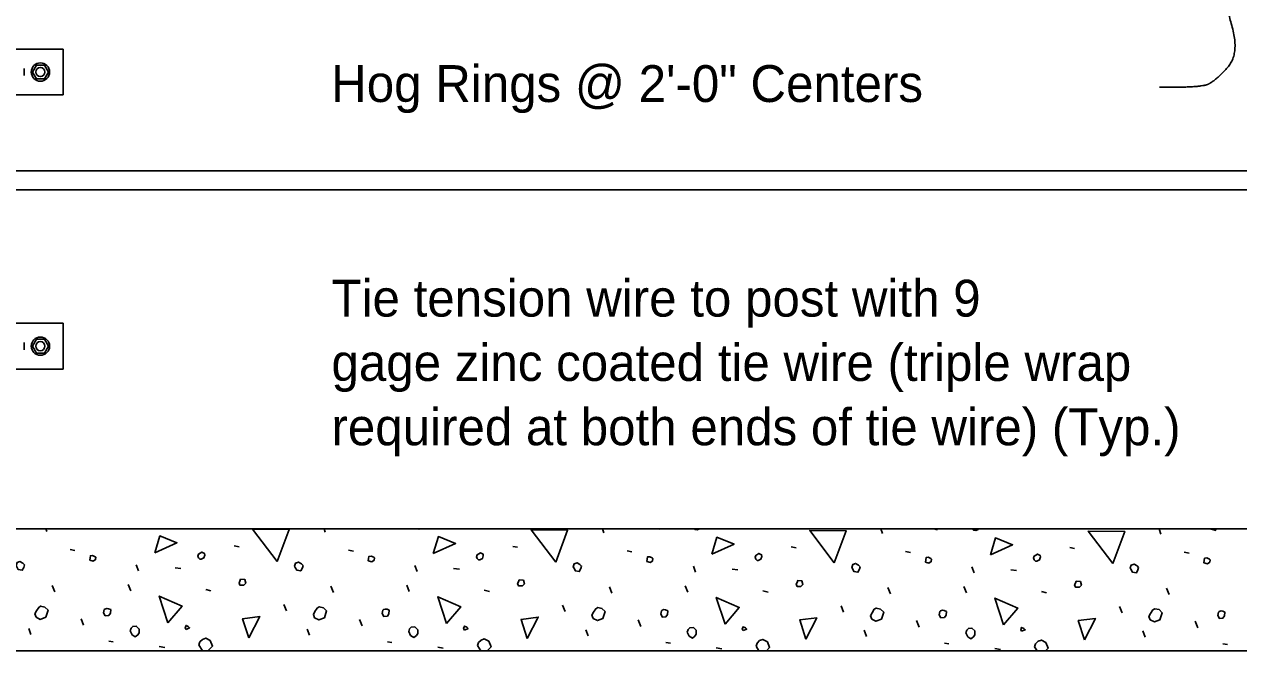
# Model space of a CAD drawing. Extents: x 0 to 41.2, y 0 to 26.
# Drawn here: x 12.4 to 19.04, y 13.8 to 17.23 of the extents above; entities that cross this region are included whole.
import ezdxf

# ---------------------------------------------------------------- set-up
doc = ezdxf.new("R2010")
doc.units = 0
for name, color, linetype in [('Dimension', 7, 'Continuous'), ('Miscellaneous', 7, 'Continuous'), ('SteelMisc', 7, 'Continuous'), ('SupstrConc', 7, 'Continuous'), ('TextStructures', 7, 'Continuous')]:
    doc.layers.add(name, color=color, linetype=linetype)

msp = doc.modelspace()

# ---------------------------------------------------------------- linework, layer by layer
at = {"layer": 'Dimension'}
msp.add_open_spline([(18.6095, 16.8868), (18.8324, 16.8833), (18.9173, 16.9222), (19.0482, 17.0709), (18.9633, 17.3684), (18.9208, 17.6337)], degree=2, dxfattribs=at)
at = {"layer": 'Miscellaneous'}
for p, q in [((12.5219, 14.4553), (12.5167, 14.4695)), ((14.0457, 14.4518), (14.0392, 14.4695)), ((15.5695, 14.4482), (15.5617, 14.4695)), ((15.8647, 14.4695), (15.8718, 14.4677)), ((17.0933, 14.4447), (17.0842, 14.4695)), ((17.3744, 14.4695), (17.3956, 14.4641)), ((18.6171, 14.4412), (18.6067, 14.4695)), ((18.8911, 14.4677), (18.9194, 14.4606)), ((12.6492, 14.3563), (12.6757, 14.351)), ((13.5472, 14.3775), (13.5737, 14.3722)), ((14.173, 14.3528), (14.1995, 14.3475)), ((15.071, 14.374), (15.0975, 14.3687)), ((16.5948, 14.3705), (16.6213, 14.3652)), ((18.1186, 14.3669), (18.1451, 14.3616)), ((15.6968, 14.3492), (15.7233, 14.3439)), ((17.2206, 14.3457), (17.2471, 14.3404)), ((18.7444, 14.3422), (18.7709, 14.3369)), ((13.0239, 14.2396), (13.0115, 14.2732)), ((13.2237, 14.2556), (13.2555, 14.252)), ((14.5477, 14.2361), (14.5354, 14.2697)), ((14.7475, 14.252), (14.7793, 14.2485)), ((16.0716, 14.2326), (16.0592, 14.2662)), ((16.2713, 14.2485), (16.3031, 14.2449)), ((17.5954, 14.229), (17.583, 14.2626)), ((17.7951, 14.2449), (17.8269, 14.2414)), ((12.5661, 14.1247), (12.5519, 14.1601)), ((12.9815, 14.13), (12.9674, 14.1654)), ((14.0899, 14.1212), (14.0757, 14.1566)), ((14.5053, 14.1265), (14.4912, 14.1619)), ((15.6137, 14.1177), (15.5996, 14.153)), ((16.0291, 14.123), (16.015, 14.1583)), ((17.5529, 14.1194), (17.5388, 14.1548)), ((13.3916, 14.1371), (13.4199, 14.13)), ((14.9154, 14.1336), (14.9437, 14.1265)), ((16.4392, 14.13), (16.4675, 14.123)), ((17.1375, 14.1141), (17.1234, 14.1495)), ((17.9631, 14.1265), (17.9913, 14.1194)), ((18.6613, 14.1106), (18.6472, 14.146)), ((13.8336, 14.0204), (13.8194, 14.0558)), ((15.3574, 14.0169), (15.3432, 14.0523)), ((16.8812, 14.0134), (16.867, 14.0487)), ((18.405, 14.0098), (18.3909, 14.0452)), ((12.7234, 13.9427), (12.7093, 13.978)), ((14.2472, 13.9391), (14.2331, 13.9745)), ((15.771, 13.9356), (15.7569, 13.9709)), ((17.2948, 13.9321), (17.2807, 13.9674)), ((18.8187, 13.9285), (18.8045, 13.9639)), ((12.4353, 13.8914), (12.4229, 13.925)), ((13.9591, 13.8879), (13.9467, 13.9214)), ((15.4829, 13.8843), (15.4705, 13.9179)), ((17.0067, 13.8808), (16.9943, 13.9144)), ((18.5305, 13.8772), (18.5181, 13.9108)), ((12.8613, 13.8543), (12.886, 13.8507)), ((13.1371, 13.826), (13.1671, 13.8207)), ((14.3851, 13.8507), (14.4099, 13.8472)), ((14.6609, 13.8224), (14.6909, 13.8171)), ((15.9089, 13.8472), (15.9337, 13.8437)), ((16.1847, 13.8189), (16.2147, 13.8136)), ((17.4327, 13.8437), (17.4575, 13.8401)), ((18.9565, 13.8401), (18.9813, 13.8366)), ((17.7085, 13.8154), (17.7386, 13.8101))]:
    msp.add_line(p, q, dxfattribs=at)
for points in [[(13.1123, 14.3386), (13.1406, 14.4306), (13.2343, 14.3934), (13.1123, 14.3386)], [(13.7823, 14.2909), (13.6479, 14.4677), (13.8477, 14.4659), (13.7823, 14.2909)], [(14.5442, 14.4695), (14.5566, 14.4677), (14.5607, 14.4695)], [(14.6361, 14.3351), (14.6644, 14.427), (14.7581, 14.3899), (14.6361, 14.3351)], [(15.3061, 14.2874), (15.1718, 14.4641), (15.3715, 14.4624), (15.3061, 14.2874)], [(16.0645, 14.4695), (16.068, 14.4659)], [(16.068, 14.4659), (16.0804, 14.4641), (16.0928, 14.4695)], [(16.1599, 14.3316), (16.1882, 14.4235), (16.2819, 14.3864), (16.1599, 14.3316)], [(16.8299, 14.2838), (16.6956, 14.4606), (16.8953, 14.4588), (16.8299, 14.2838)], [(17.5848, 14.4695), (17.5918, 14.4624)], [(17.5918, 14.4624), (17.6042, 14.4606), (17.6166, 14.4659), (17.6178, 14.4695)], [(17.6838, 14.328), (17.712, 14.42), (17.8057, 14.3828), (17.6838, 14.328)], [(18.3537, 14.2803), (18.2194, 14.4571), (18.4191, 14.4553), (18.3537, 14.2803)], [(12.3575, 14.2626), (12.3663, 14.2467), (12.3875, 14.2432), (12.3964, 14.2591), (12.3999, 14.2732), (12.3911, 14.2821), (12.3752, 14.2909), (12.3592, 14.2856), (12.3539, 14.2697), (12.3575, 14.2626)], [(12.757, 14.298), (12.7764, 14.2927), (12.7888, 14.3015), (12.7906, 14.3139), (12.787, 14.3174), (12.7729, 14.3245), (12.7605, 14.3227), (12.7588, 14.3104), (12.757, 14.298)], [(13.3598, 14.3033), (13.3669, 14.3033), (13.381, 14.3104), (13.3863, 14.3263), (13.3845, 14.3351), (13.3704, 14.3422), (13.3527, 14.3316), (13.3492, 14.321), (13.3527, 14.3104), (13.3598, 14.3033)], [(13.8813, 14.2591), (13.8901, 14.2432), (13.9113, 14.2396), (13.9202, 14.2556), (13.9237, 14.2697), (13.9149, 14.2785), (13.899, 14.2874), (13.8831, 14.2821), (13.8778, 14.2662), (13.8813, 14.2591)], [(14.2808, 14.2944), (14.3003, 14.2891), (14.3126, 14.298), (14.3144, 14.3104), (14.3109, 14.3139), (14.2967, 14.321), (14.2843, 14.3192), (14.2826, 14.3068), (14.2808, 14.2944)], [(14.8836, 14.2997), (14.8907, 14.2997), (14.9048, 14.3068), (14.9101, 14.3227), (14.9084, 14.3316), (14.8942, 14.3386), (14.8765, 14.328), (14.873, 14.3174), (14.8765, 14.3068), (14.8836, 14.2997)], [(15.4051, 14.2556), (15.4139, 14.2396), (15.4352, 14.2361), (15.444, 14.252), (15.4475, 14.2662), (15.4387, 14.275), (15.4228, 14.2838), (15.4069, 14.2785), (15.4016, 14.2626), (15.4051, 14.2556)], [(15.8046, 14.2909), (15.8241, 14.2856), (15.8364, 14.2944), (15.8382, 14.3068), (15.8347, 14.3104), (15.8205, 14.3174), (15.8082, 14.3157), (15.8064, 14.3033), (15.8046, 14.2909)], [(16.4074, 14.2962), (16.4145, 14.2962), (16.4286, 14.3033), (16.4339, 14.3192), (16.4322, 14.328), (16.418, 14.3351), (16.4004, 14.3245), (16.3968, 14.3139), (16.4004, 14.3033), (16.4074, 14.2962)], [(17.3284, 14.2874), (17.3479, 14.2821), (17.3603, 14.2909), (17.362, 14.3033), (17.3585, 14.3068), (17.3443, 14.3139), (17.332, 14.3121), (17.3302, 14.2997), (17.3284, 14.2874)], [(17.9312, 14.2927), (17.9383, 14.2927), (17.9525, 14.2997), (17.9578, 14.3157), (17.956, 14.3245), (17.9419, 14.3316), (17.9242, 14.321), (17.9206, 14.3104), (17.9242, 14.2997), (17.9312, 14.2927)], [(18.8523, 14.2838), (18.8717, 14.2785), (18.8841, 14.2874), (18.8858, 14.2997), (18.8823, 14.3033), (18.8682, 14.3104), (18.8558, 14.3086), (18.854, 14.2962), (18.8523, 14.2838)], [(16.9289, 14.252), (16.9378, 14.2361), (16.959, 14.2326), (16.9678, 14.2485), (16.9713, 14.2626), (16.9625, 14.2715), (16.9466, 14.2803), (16.9307, 14.275), (16.9254, 14.2591), (16.9289, 14.252)], [(18.4527, 14.2485), (18.4616, 14.2326), (18.4828, 14.229), (18.4916, 14.2449), (18.4952, 14.2591), (18.4863, 14.2679), (18.4704, 14.2768), (18.4545, 14.2715), (18.4492, 14.2556), (18.4527, 14.2485)], [(13.579, 14.1619), (13.6002, 14.1619), (13.6108, 14.1725), (13.6055, 14.1919), (13.5825, 14.1937), (13.579, 14.1831), (13.5737, 14.1742), (13.579, 14.1619), (13.5755, 14.1654)], [(15.1028, 14.1583), (15.124, 14.1583), (15.1346, 14.1689), (15.1293, 14.1884), (15.1064, 14.1901), (15.1028, 14.1795), (15.0975, 14.1707), (15.1028, 14.1583), (15.0993, 14.1619)], [(16.6266, 14.1548), (16.6478, 14.1548), (16.6585, 14.1654), (16.6531, 14.1848), (16.6302, 14.1866), (16.6266, 14.176), (16.6213, 14.1672), (16.6266, 14.1548), (16.6231, 14.1583)], [(18.1504, 14.1513), (18.1717, 14.1513), (18.1823, 14.1619), (18.177, 14.1813), (18.154, 14.1831), (18.1504, 14.1725), (18.1451, 14.1636), (18.1504, 14.1513), (18.1469, 14.1548)], [(13.1848, 13.955), (13.1371, 14.1018), (13.2626, 14.047), (13.1848, 13.955)], [(14.7086, 13.9515), (14.6609, 14.0982), (14.7864, 14.0434), (14.7086, 13.9515)], [(16.2324, 13.948), (16.1847, 14.0947), (16.3102, 14.0399), (16.2324, 13.948)], [(17.7562, 13.9444), (17.7085, 14.0911), (17.834, 14.0363), (17.7562, 13.9444)], [(12.4635, 13.9869), (12.4865, 13.9745), (12.5166, 13.9869), (12.5289, 14.024), (12.5113, 14.0417), (12.4883, 14.047), (12.4777, 14.0399), (12.4653, 14.0204), (12.4565, 14.0045), (12.4635, 13.9869)], [(12.833, 14.0098), (12.8418, 13.9939), (12.8613, 13.9957), (12.8701, 14.0081), (12.8719, 14.0275), (12.8595, 14.0328), (12.8507, 14.0346), (12.8401, 14.031), (12.8365, 14.0275), (12.833, 14.0098)], [(13.9874, 13.9833), (14.0103, 13.9709), (14.0404, 13.9833), (14.0528, 14.0204), (14.0351, 14.0381), (14.0121, 14.0434), (14.0015, 14.0363), (13.9891, 14.0169), (13.9803, 14.001), (13.9874, 13.9833)], [(14.3568, 14.0063), (14.3657, 13.9904), (14.3851, 13.9922), (14.3939, 14.0045), (14.3957, 14.024), (14.3833, 14.0293), (14.3745, 14.031), (14.3639, 14.0275), (14.3604, 14.024), (14.3568, 14.0063)], [(15.5112, 13.9798), (15.5342, 13.9674), (15.5642, 13.9798), (15.5766, 14.0169), (15.5589, 14.0346), (15.5359, 14.0399), (15.5253, 14.0328), (15.5129, 14.0134), (15.5041, 13.9975), (15.5112, 13.9798)], [(15.8806, 14.0028), (15.8895, 13.9869), (15.9089, 13.9886), (15.9178, 14.001), (15.9195, 14.0204), (15.9072, 14.0257), (15.8983, 14.0275), (15.8877, 14.024), (15.8842, 14.0204), (15.8806, 14.0028)], [(17.035, 13.9762), (17.058, 13.9639), (17.088, 13.9762), (17.1004, 14.0134), (17.0827, 14.031), (17.0597, 14.0363), (17.0491, 14.0293), (17.0368, 14.0098), (17.0279, 13.9939), (17.035, 13.9762)], [(17.4044, 13.9992), (17.4133, 13.9833), (17.4327, 13.9851), (17.4416, 13.9975), (17.4433, 14.0169), (17.431, 14.0222), (17.4221, 14.024), (17.4115, 14.0204), (17.408, 14.0169), (17.4044, 13.9992)], [(18.5588, 13.9727), (18.5818, 13.9603), (18.6118, 13.9727), (18.6242, 14.0098), (18.6065, 14.0275), (18.5836, 14.0328), (18.5729, 14.0257), (18.5606, 14.0063), (18.5517, 13.9904), (18.5588, 13.9727)], [(18.9283, 13.9957), (18.9371, 13.9798), (18.9565, 13.9815), (18.9654, 13.9939), (18.9672, 14.0134), (18.9548, 14.0187), (18.9459, 14.0204), (18.9353, 14.0169), (18.9318, 14.0134), (18.9283, 13.9957)], [(13.6267, 13.8737), (13.5931, 13.978), (13.6868, 13.9904), (13.6267, 13.8737)], [(15.1505, 13.8702), (15.117, 13.9745), (15.2107, 13.9869), (15.1505, 13.8702)], [(16.6744, 13.8666), (16.6408, 13.9709), (16.7345, 13.9833), (16.6744, 13.8666)], [(18.1982, 13.8631), (18.1646, 13.9674), (18.2583, 13.9798), (18.1982, 13.8631)], [(12.978, 13.9108), (12.9886, 13.8896), (13.0062, 13.879), (13.0204, 13.8896), (13.0275, 13.9002), (13.0275, 13.9214), (13.0115, 13.9374), (12.9921, 13.9356), (12.9833, 13.9267), (12.978, 13.9108)], [(13.2838, 13.9197), (13.3032, 13.9285), (13.2962, 13.9356), (13.2838, 13.9409), (13.2785, 13.9285), (13.2838, 13.9197)], [(14.5018, 13.9073), (14.5124, 13.8861), (14.5301, 13.8755), (14.5442, 13.8861), (14.5513, 13.8967), (14.5513, 13.9179), (14.5354, 13.9338), (14.5159, 13.9321), (14.5071, 13.9232), (14.5018, 13.9073)], [(14.8076, 13.9161), (14.827, 13.925), (14.82, 13.9321), (14.8076, 13.9374), (14.8023, 13.925), (14.8076, 13.9161)], [(16.0256, 13.9038), (16.0362, 13.8826), (16.0539, 13.8719), (16.068, 13.8826), (16.0751, 13.8932), (16.0751, 13.9144), (16.0592, 13.9303), (16.0397, 13.9285), (16.0309, 13.9197), (16.0256, 13.9038)], [(16.3314, 13.9126), (16.3509, 13.9214), (16.3438, 13.9285), (16.3314, 13.9338), (16.3261, 13.9214), (16.3314, 13.9126)], [(17.5494, 13.9002), (17.56, 13.879), (17.5777, 13.8684), (17.5918, 13.879), (17.5989, 13.8896), (17.5989, 13.9108), (17.583, 13.9267), (17.5635, 13.925), (17.5547, 13.9161), (17.5494, 13.9002)], [(17.8552, 13.9091), (17.8747, 13.9179), (17.8676, 13.925), (17.8552, 13.9303), (17.8499, 13.9179), (17.8552, 13.9091)], [(13.4038, 13.8028), (13.4093, 13.8083), (13.4287, 13.8278), (13.4164, 13.8578), (13.3916, 13.8719), (13.3739, 13.8649), (13.3598, 13.8507), (13.3545, 13.8348)], [(13.3545, 13.8348), (13.3743, 13.8028)], [(14.9311, 13.8028), (14.9331, 13.8048), (14.9526, 13.8242), (14.9402, 13.8543), (14.9154, 13.8684), (14.8978, 13.8613), (14.8836, 13.8472), (14.8783, 13.8313)], [(14.8783, 13.8313), (14.896, 13.8028)], [(16.4585, 13.8028), (16.4764, 13.8207), (16.464, 13.8507), (16.4392, 13.8649), (16.4216, 13.8578), (16.4074, 13.8437), (16.4021, 13.8278)], [(16.4021, 13.8278), (16.4176, 13.8028)], [(17.9858, 13.8028), (18.0002, 13.8171), (17.9878, 13.8472), (17.9631, 13.8613), (17.9454, 13.8543), (17.9312, 13.8401), (17.9259, 13.8242)], [(17.9259, 13.8242), (17.9392, 13.8028)]]:
    msp.add_lwpolyline(points, dxfattribs=at)
at = {"layer": 'SteelMisc'}
for p, q in [((11.8002, 17.0944), (12.6122, 17.0944)), ((12.6122, 17.0944), (12.6122, 16.8444)), ((12.399, 16.95), (12.399, 16.9889)), ((12.6122, 16.8444), (11.8002, 16.8444)), ((11.8002, 15.5944), (12.6122, 15.5944)), ((12.6122, 15.5944), (12.6122, 15.3444)), ((12.399, 15.45), (12.399, 15.4889)), ((12.6122, 15.3444), (11.8002, 15.3444))]:
    msp.add_line(p, q, dxfattribs=at)
for points in [[(12.4655, 17.007), (12.5089, 17.007), (12.5305, 16.9694), (12.5089, 16.9319), (12.4655, 16.9319), (12.4439, 16.9694)], [(12.4655, 15.507), (12.5089, 15.507), (12.5305, 15.4694), (12.5089, 15.4319), (12.4655, 15.4319), (12.4439, 15.4694)]]:
    msp.add_lwpolyline(points, close=True, dxfattribs=at)
for centre, radius in [((12.4872, 16.9694), 0.05), ((12.4872, 16.9694), 0.025), ((12.4872, 15.4694), 0.05), ((12.4872, 15.4694), 0.025)]:
    msp.add_circle(centre, radius, dxfattribs=at)
at = {"layer": 'SupstrConc'}
for p, q in [((12.3521, 16.4295), (22.0604, 16.4295)), ((12.3521, 16.3254), (22.0604, 16.3254)), ((0.8193, 14.4695), (23.5931, 14.4695)), ((0.8193, 13.8028), (23.5931, 13.8028))]:
    msp.add_line(p, q, dxfattribs=at)

# ---------------------------------------------------------------- texts
at = {"layer": 'Dimension'}
for s, p in [('Tie tension wire to post with 9 ', (14.0794, 15.6312)), ('gage zinc coated tie wire (triple wrap ', (14.0794, 15.2792)), ('required at both ends of tie wire) (Typ.)', (14.0794, 14.9272))]:
    msp.add_text(s, height=0.2016, dxfattribs=at).set_placement(p)
at = {"layer": 'TextStructures'}
msp.add_text('Hog Rings @ 2\'-0" Centers', height=0.2016, dxfattribs=at).set_placement((14.0777, 16.8056))

doc.saveas('drawing.dxf')
